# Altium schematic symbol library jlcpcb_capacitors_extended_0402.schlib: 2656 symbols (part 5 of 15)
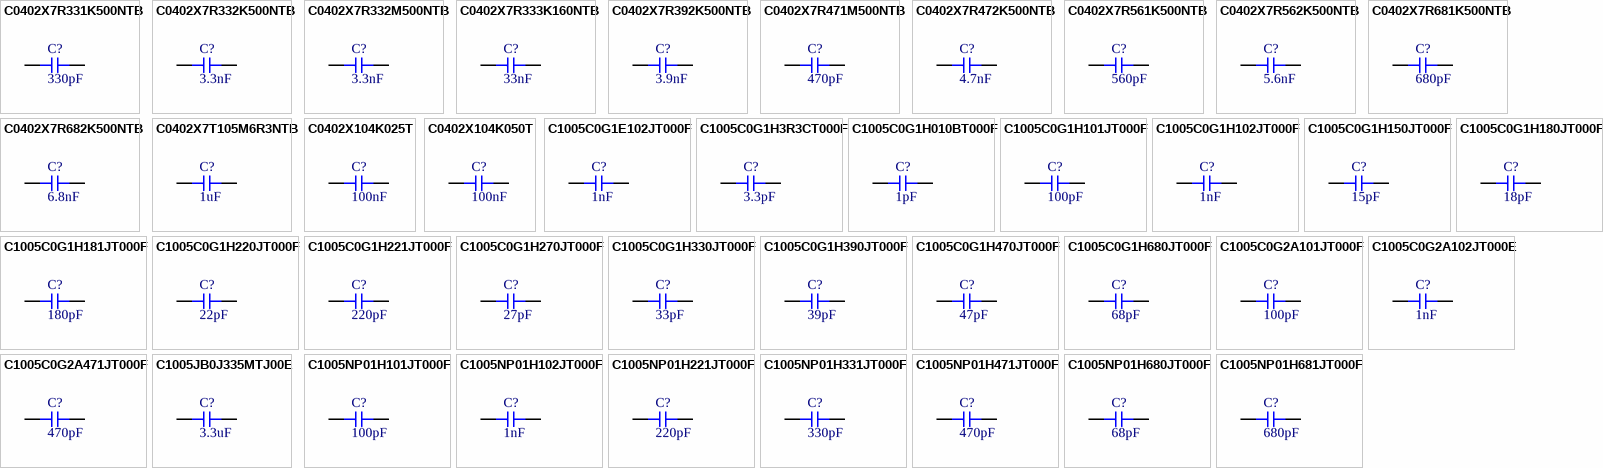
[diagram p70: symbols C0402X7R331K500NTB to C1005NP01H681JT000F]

## C0402X7R331K500NTB
designator C?  Capacitance: 330pF  (hidden comment: *)
Capacitor, Ceramic (MLCC), 330pF, ±10%, 50V, X7R, ±10%, SMD 0402; Manufacturer: EYANG(Shenzhen Eyang Tech Development); Manufacturer Part Number: C0402X7R331K500NTB
footprint CAP-0402 (0402 (1005M) Capacitor)
pins: 1, 2

## C0402X7R332K500NTB
designator C?  Capacitance: 3.3nF  (hidden comment: *)
Capacitor, Ceramic (MLCC), 3.3nF, ±10%, 50V, X7R, ±10%, SMD 0402; Manufacturer: EYANG(Shenzhen Eyang Tech Development); Manufacturer Part Number: C0402X7R332K500NTB
footprint CAP-0402 (0402 (1005M) Capacitor)
pins: 1, 2

## C0402X7R332M500NTB
designator C?  Capacitance: 3.3nF  (hidden comment: *)
Capacitor, Ceramic (MLCC), 3.3nF, ±20%, 50V, X7R, ±20%, SMD 0402; Manufacturer: EYANG(Shenzhen Eyang Tech Development); Manufacturer Part Number: C0402X7R332M500NTB
footprint CAP-0402 (0402 (1005M) Capacitor)
pins: 1, 2

## C0402X7R333K160NTB
designator C?  Capacitance: 33nF  (hidden comment: *)
Capacitor, Ceramic (MLCC), 33nF, ±10%, 16V, X7R, ±10%, SMD 0402; Manufacturer: EYANG(Shenzhen Eyang Tech Development); Manufacturer Part Number: C0402X7R333K160NTB
footprint CAP-0402 (0402 (1005M) Capacitor)
pins: 1, 2

## C0402X7R392K500NTB
designator C?  Capacitance: 3.9nF  (hidden comment: *)
Capacitor, Ceramic (MLCC), 3.9nF, ±10%, 50V, X7R, ±10%, SMD 0402; Manufacturer: EYANG(Shenzhen Eyang Tech Development); Manufacturer Part Number: C0402X7R392K500NTB
footprint CAP-0402 (0402 (1005M) Capacitor)
pins: 1, 2

## C0402X7R471M500NTB
designator C?  Capacitance: 470pF  (hidden comment: *)
Capacitor, Ceramic (MLCC), 470pF, ±20%, 50V, X7R, ±20%, SMD 0402; Manufacturer: EYANG(Shenzhen Eyang Tech Development); Manufacturer Part Number: C0402X7R471M500NTB
footprint CAP-0402 (0402 (1005M) Capacitor)
pins: 1, 2

## C0402X7R472K500NTB
designator C?  Capacitance: 4.7nF  (hidden comment: *)
Capacitor, Ceramic (MLCC), 4.7nF, ±10%, 50V, X7R, ±10%, SMD 0402; Manufacturer: EYANG(Shenzhen Eyang Tech Development); Manufacturer Part Number: C0402X7R472K500NTB
footprint CAP-0402 (0402 (1005M) Capacitor)
pins: 1, 2

## C0402X7R561K500NTB
designator C?  Capacitance: 560pF  (hidden comment: *)
Capacitor, Ceramic (MLCC), 560pF, ±10%, 50V, X7R, ±10%, SMD 0402; Manufacturer: EYANG(Shenzhen Eyang Tech Development); Manufacturer Part Number: C0402X7R561K500NTB
footprint CAP-0402 (0402 (1005M) Capacitor)
pins: 1, 2

## C0402X7R562K500NTB
designator C?  Capacitance: 5.6nF  (hidden comment: *)
Capacitor, Ceramic (MLCC), 5.6nF, ±10%, 50V, X7R, ±10%, SMD 0402; Manufacturer: EYANG(Shenzhen Eyang Tech Development); Manufacturer Part Number: C0402X7R562K500NTB
footprint CAP-0402 (0402 (1005M) Capacitor)
pins: 1, 2

## C0402X7R681K500NTB
designator C?  Capacitance: 680pF  (hidden comment: *)
Capacitor, Ceramic (MLCC), 680pF, ±10%, 50V, X7R, ±10%, SMD 0402; Manufacturer: EYANG(Shenzhen Eyang Tech Development); Manufacturer Part Number: C0402X7R681K500NTB
footprint CAP-0402 (0402 (1005M) Capacitor)
pins: 1, 2

## C0402X7R682K500NTB
designator C?  Capacitance: 6.8nF  (hidden comment: *)
Capacitor, Ceramic (MLCC), 6.8nF, ±10%, 50V, X7R, ±10%, SMD 0402; Manufacturer: EYANG(Shenzhen Eyang Tech Development); Manufacturer Part Number: C0402X7R682K500NTB
footprint CAP-0402 (0402 (1005M) Capacitor)
pins: 1, 2

## C0402X7T105M6R3NTB
designator C?  Capacitance: 1uF  (hidden comment: *)
Capacitor, Ceramic (MLCC), 1uF, ±20%, 6.3V, X7T, ±20%, SMD 0402; Manufacturer: EYANG(Shenzhen Eyang Tech Development); Manufacturer Part Number: C0402X7T105M6R3NTB
footprint CAP-0402 (0402 (1005M) Capacitor)
pins: 1, 2

## C0402X104K025T
designator C?  Capacitance: 100nF  (hidden comment: *)
Capacitor, Ceramic (MLCC), 100nF, ±10%, 25V, X7R, ±10%, SMD 0402; Manufacturer: IHHEC(HOLY STONE ENTERPRISE CO., LTD); Manufacturer Part Number: C0402X104K025T
footprint CAP-0402 (0402 (1005M) Capacitor)
pins: 1, 2

## C0402X104K050T
designator C?  Capacitance: 100nF  (hidden comment: *)
Capacitor, Ceramic (MLCC), 100nF, ±10%, 50V, X7R, ±10%, SMD 0402; Manufacturer: IHHEC(HOLY STONE ENTERPRISE CO., LTD); Manufacturer Part Number: C0402X104K050T
footprint CAP-0402 (0402 (1005M) Capacitor)
pins: 1, 2

## C1005C0G1E102JT000F
designator C?  Capacitance: 1nF  (hidden comment: *)
Capacitor, Ceramic (MLCC), 1nF, ±5%, 25V, C0G, ±5%, SMD 0402; Manufacturer: TDK; Manufacturer Part Number: C1005C0G1E102JT000F
footprint CAP-0402 (0402 (1005M) Capacitor)
pins: 1, 2

## C1005C0G1H3R3CT000F
designator C?  Capacitance: 3.3pF  (hidden comment: *)
Capacitor, Ceramic (MLCC), 3.3pF, ±0.25pF, 50V, C0G, ±0.25pF, SMD 0402; Manufacturer: TDK; Manufacturer Part Number: C1005C0G1H3R3CT000F
footprint CAP-0402 (0402 (1005M) Capacitor)
pins: 1, 2

## C1005C0G1H010BT000F
designator C?  Capacitance: 1pF  (hidden comment: *)
Capacitor, Ceramic (MLCC), 1pF, ±0.1pF, 50V, C0G, ±0.1pF, SMD 0402; Manufacturer: TDK; Manufacturer Part Number: C1005C0G1H010BT000F
footprint CAP-0402 (0402 (1005M) Capacitor)
pins: 1, 2

## C1005C0G1H101JT000F
designator C?  Capacitance: 100pF  (hidden comment: *)
Capacitor, Ceramic (MLCC), 100pF, ±5%, 50V, C0G, ±5%, SMD 0402; Manufacturer: TDK; Manufacturer Part Number: C1005C0G1H101JT000F
footprint CAP-0402 (0402 (1005M) Capacitor)
pins: 1, 2

## C1005C0G1H102JT000F
designator C?  Capacitance: 1nF  (hidden comment: *)
Capacitor, Ceramic (MLCC), 1nF, ±5%, 50V, C0G, ±5%, SMD 0402; Manufacturer: TDK; Manufacturer Part Number: C1005C0G1H102JT000F
footprint CAP-0402 (0402 (1005M) Capacitor)
pins: 1, 2

## C1005C0G1H150JT000F
designator C?  Capacitance: 15pF  (hidden comment: *)
Capacitor, Ceramic (MLCC), 15pF, ±5%, 50V, C0G, ±5%, SMD 0402; Manufacturer: TDK; Manufacturer Part Number: C1005C0G1H150JT000F
footprint CAP-0402 (0402 (1005M) Capacitor)
pins: 1, 2

## C1005C0G1H180JT000F
designator C?  Capacitance: 18pF  (hidden comment: *)
Capacitor, Ceramic (MLCC), 18pF, ±5%, 50V, C0G, ±5%, SMD 0402; Manufacturer: TDK; Manufacturer Part Number: C1005C0G1H180JT000F
footprint CAP-0402 (0402 (1005M) Capacitor)
pins: 1, 2

## C1005C0G1H181JT000F
designator C?  Capacitance: 180pF  (hidden comment: *)
Capacitor, Ceramic (MLCC), 180pF, ±5%, 50V, C0G, ±5%, SMD 0402; Manufacturer: TDK; Manufacturer Part Number: C1005C0G1H181JT000F
footprint CAP-0402 (0402 (1005M) Capacitor)
pins: 1, 2

## C1005C0G1H220JT000F
designator C?  Capacitance: 22pF  (hidden comment: *)
Capacitor, Ceramic (MLCC), 22pF, ±5%, 50V, C0G, ±5%, SMD 0402; Manufacturer: TDK; Manufacturer Part Number: C1005C0G1H220JT000F
footprint CAP-0402 (0402 (1005M) Capacitor)
pins: 1, 2

## C1005C0G1H221JT000F
designator C?  Capacitance: 220pF  (hidden comment: *)
Capacitor, Ceramic (MLCC), 220pF, ±5%, 50V, C0G, ±5%, SMD 0402; Manufacturer: TDK; Manufacturer Part Number: C1005C0G1H221JT000F
footprint CAP-0402 (0402 (1005M) Capacitor)
pins: 1, 2

## C1005C0G1H270JT000F
designator C?  Capacitance: 27pF  (hidden comment: *)
Capacitor, Ceramic (MLCC), 27pF, ±5%, 50V, C0G, ±5%, SMD 0402; Manufacturer: TDK; Manufacturer Part Number: C1005C0G1H270JT000F
footprint CAP-0402 (0402 (1005M) Capacitor)
pins: 1, 2

## C1005C0G1H330JT000F
designator C?  Capacitance: 33pF  (hidden comment: *)
Capacitor, Ceramic (MLCC), 33pF, ±5%, 50V, C0G, ±5%, SMD 0402; Manufacturer: TDK; Manufacturer Part Number: C1005C0G1H330JT000F
footprint CAP-0402 (0402 (1005M) Capacitor)
pins: 1, 2

## C1005C0G1H390JT000F
designator C?  Capacitance: 39pF  (hidden comment: *)
Capacitor, Ceramic (MLCC), 39pF, ±5%, 50V, C0G, ±5%, SMD 0402; Manufacturer: TDK; Manufacturer Part Number: C1005C0G1H390JT000F
footprint CAP-0402 (0402 (1005M) Capacitor)
pins: 1, 2

## C1005C0G1H470JT000F
designator C?  Capacitance: 47pF  (hidden comment: *)
Capacitor, Ceramic (MLCC), 47pF, ±5%, 50V, C0G, ±5%, SMD 0402; Manufacturer: TDK; Manufacturer Part Number: C1005C0G1H470JT000F
footprint CAP-0402 (0402 (1005M) Capacitor)
pins: 1, 2

## C1005C0G1H680JT000F
designator C?  Capacitance: 68pF  (hidden comment: *)
Capacitor, Ceramic (MLCC), 68pF, ±5%, 50V, C0G, ±5%, SMD 0402; Manufacturer: TDK; Manufacturer Part Number: C1005C0G1H680JT000F
footprint CAP-0402 (0402 (1005M) Capacitor)
pins: 1, 2

## C1005C0G2A101JT000F
designator C?  Capacitance: 100pF  (hidden comment: *)
Capacitor, Ceramic (MLCC), 100pF, ±5%, 100V, C0G, ±5%, SMD 0402; Manufacturer: TDK; Manufacturer Part Number: C1005C0G2A101JT000F
footprint CAP-0402 (0402 (1005M) Capacitor)
pins: 1, 2

## C1005C0G2A102JT000E
designator C?  Capacitance: 1nF  (hidden comment: *)
Capacitor, Ceramic (MLCC), 1nF, ±5%, 100V, C0G, ±5%, SMD 0402; Manufacturer: TDK; Manufacturer Part Number: C1005C0G2A102JT000E
footprint CAP-0402 (0402 (1005M) Capacitor)
pins: 1, 2

## C1005C0G2A471JT000F
designator C?  Capacitance: 470pF  (hidden comment: *)
Capacitor, Ceramic (MLCC), 470pF, ±5%, 100V, C0G, ±5%, SMD 0402; Manufacturer: TDK; Manufacturer Part Number: C1005C0G2A471JT000F
footprint CAP-0402 (0402 (1005M) Capacitor)
pins: 1, 2

## C1005JB0J335MTJ00E
designator C?  Capacitance: 3.3uF  (hidden comment: *)
Capacitor, Ceramic (MLCC), 3.3uF, ±20%, 6.3V, ±20%, SMD 0402; Manufacturer: TDK; Manufacturer Part Number: C1005JB0J335MTJ00E
footprint CAP-0402 (0402 (1005M) Capacitor)
pins: 1, 2

## C1005NP01H101JT000F
designator C?  Capacitance: 100pF  (hidden comment: *)
Capacitor, Ceramic (MLCC), 100pF, ±5%, 50V, NP0, ±5%, SMD 0402; Manufacturer: TDK; Manufacturer Part Number: C1005NP01H101JT000F
footprint CAP-0402 (0402 (1005M) Capacitor)
pins: 1, 2

## C1005NP01H102JT000F
designator C?  Capacitance: 1nF  (hidden comment: *)
Capacitor, Ceramic (MLCC), 1nF, ±5%, 50V, NP0, ±5%, SMD 0402; Manufacturer: TDK; Manufacturer Part Number: C1005NP01H102JT000F
footprint CAP-0402 (0402 (1005M) Capacitor)
pins: 1, 2

## C1005NP01H221JT000F
designator C?  Capacitance: 220pF  (hidden comment: *)
Capacitor, Ceramic (MLCC), 220pF, ±5%, 50V, NP0, ±5%, SMD 0402; Manufacturer: TDK; Manufacturer Part Number: C1005NP01H221JT000F
footprint CAP-0402 (0402 (1005M) Capacitor)
pins: 1, 2

## C1005NP01H331JT000F
designator C?  Capacitance: 330pF  (hidden comment: *)
Capacitor, Ceramic (MLCC), 330pF, ±5%, 50V, NP0, ±5%, SMD 0402; Manufacturer: TDK; Manufacturer Part Number: C1005NP01H331JT000F
footprint CAP-0402 (0402 (1005M) Capacitor)
pins: 1, 2

## C1005NP01H471JT000F
designator C?  Capacitance: 470pF  (hidden comment: *)
Capacitor, Ceramic (MLCC), 470pF, ±5%, 50V, NP0, ±5%, SMD 0402; Manufacturer: TDK; Manufacturer Part Number: C1005NP01H471JT000F
footprint CAP-0402 (0402 (1005M) Capacitor)
pins: 1, 2

## C1005NP01H680JT000F
designator C?  Capacitance: 68pF  (hidden comment: *)
Capacitor, Ceramic (MLCC), 68pF, ±5%, 50V, NP0, ±5%, SMD 0402; Manufacturer: TDK; Manufacturer Part Number: C1005NP01H680JT000F
footprint CAP-0402 (0402 (1005M) Capacitor)
pins: 1, 2

## C1005NP01H681JT000F
designator C?  Capacitance: 680pF  (hidden comment: *)
Capacitor, Ceramic (MLCC), 680pF, ±5%, 50V, NP0, ±5%, SMD 0402; Manufacturer: TDK; Manufacturer Part Number: C1005NP01H681JT000F
footprint CAP-0402 (0402 (1005M) Capacitor)
pins: 1, 2

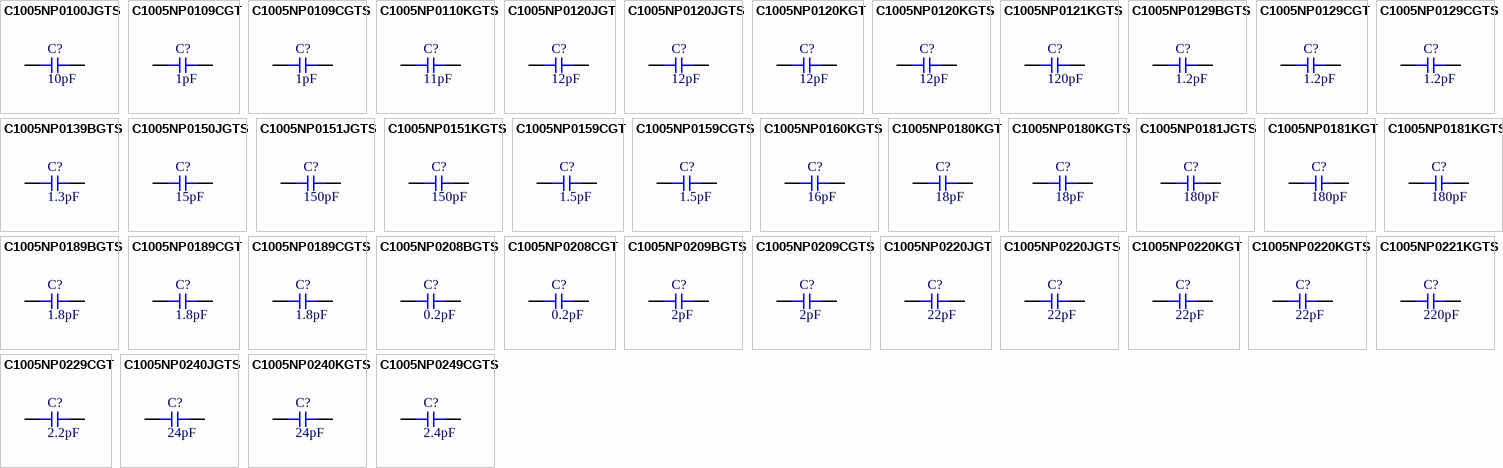
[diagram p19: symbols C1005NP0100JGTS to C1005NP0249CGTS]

## C1005NP0100JGTS
designator C?  Capacitance: 10pF  (hidden comment: *)
Capacitor, Ceramic (MLCC), 10pF, ±5%, 50V, NP0, ±5%, SMD 0402; Manufacturer: Darfon Elec; Manufacturer Part Number: C1005NP0100JGTS
footprint CAP-0402 (0402 (1005M) Capacitor)
pins: 1, 2

## C1005NP0109CGT
designator C?  Capacitance: 1pF  (hidden comment: *)
Capacitor, Ceramic (MLCC), 1pF, ±0.25pF, 50V, NP0, ±0.25pF, SMD 0402; Manufacturer: Darfon Elec; Manufacturer Part Number: C1005NP0109CGT
footprint CAP-0402 (0402 (1005M) Capacitor)
pins: 1, 2

## C1005NP0109CGTS
designator C?  Capacitance: 1pF  (hidden comment: *)
Capacitor, Ceramic (MLCC), 1pF, ±0.25pF, 50V, NP0, ±0.25pF, SMD 0402; Manufacturer: Darfon Elec; Manufacturer Part Number: C1005NP0109CGTS
footprint CAP-0402 (0402 (1005M) Capacitor)
pins: 1, 2

## C1005NP0110KGTS
designator C?  Capacitance: 11pF  (hidden comment: *)
Capacitor, Ceramic (MLCC), 11pF, ±10%, 50V, NP0, ±10%, SMD 0402; Manufacturer: Darfon Elec; Manufacturer Part Number: C1005NP0110KGTS
footprint CAP-0402 (0402 (1005M) Capacitor)
pins: 1, 2

## C1005NP0120JGT
designator C?  Capacitance: 12pF  (hidden comment: *)
Capacitor, Ceramic (MLCC), 12pF, ±5%, 50V, NP0, ±5%, SMD 0402; Manufacturer: Darfon Elec; Manufacturer Part Number: C1005NP0120JGT
footprint CAP-0402 (0402 (1005M) Capacitor)
pins: 1, 2

## C1005NP0120JGTS
designator C?  Capacitance: 12pF  (hidden comment: *)
Capacitor, Ceramic (MLCC), 12pF, ±5%, 50V, NP0, ±5%, SMD 0402; Manufacturer: Darfon Elec; Manufacturer Part Number: C1005NP0120JGTS
footprint CAP-0402 (0402 (1005M) Capacitor)
pins: 1, 2

## C1005NP0120KGT
designator C?  Capacitance: 12pF  (hidden comment: *)
Capacitor, Ceramic (MLCC), 12pF, ±10%, 50V, NP0, ±10%, SMD 0402; Manufacturer: Darfon Elec; Manufacturer Part Number: C1005NP0120KGT
footprint CAP-0402 (0402 (1005M) Capacitor)
pins: 1, 2

## C1005NP0120KGTS
designator C?  Capacitance: 12pF  (hidden comment: *)
Capacitor, Ceramic (MLCC), 12pF, ±10%, 50V, NP0, ±10%, SMD 0402; Manufacturer: Darfon Elec; Manufacturer Part Number: C1005NP0120KGTS
footprint CAP-0402 (0402 (1005M) Capacitor)
pins: 1, 2

## C1005NP0121KGTS
designator C?  Capacitance: 120pF  (hidden comment: *)
Capacitor, Ceramic (MLCC), 120pF, ±10%, 50V, NP0, ±10%, SMD 0402; Manufacturer: Darfon Elec; Manufacturer Part Number: C1005NP0121KGTS
footprint CAP-0402 (0402 (1005M) Capacitor)
pins: 1, 2

## C1005NP0129BGTS
designator C?  Capacitance: 1.2pF  (hidden comment: *)
Capacitor, Ceramic (MLCC), 1.2pF, ±0.1pF, 50V, NP0, ±0.1pF, SMD 0402; Manufacturer: Darfon Elec; Manufacturer Part Number: C1005NP0129BGTS
footprint CAP-0402 (0402 (1005M) Capacitor)
pins: 1, 2

## C1005NP0129CGT
designator C?  Capacitance: 1.2pF  (hidden comment: *)
Capacitor, Ceramic (MLCC), 1.2pF, ±0.25pF, 50V, NP0, ±0.25pF, SMD 0402; Manufacturer: Darfon Elec; Manufacturer Part Number: C1005NP0129CGT
footprint CAP-0402 (0402 (1005M) Capacitor)
pins: 1, 2

## C1005NP0129CGTS
designator C?  Capacitance: 1.2pF  (hidden comment: *)
Capacitor, Ceramic (MLCC), 1.2pF, ±0.25pF, 50V, NP0, ±0.25pF, SMD 0402; Manufacturer: Darfon Elec; Manufacturer Part Number: C1005NP0129CGTS
footprint CAP-0402 (0402 (1005M) Capacitor)
pins: 1, 2

## C1005NP0139BGTS
designator C?  Capacitance: 1.3pF  (hidden comment: *)
Capacitor, Ceramic (MLCC), 1.3pF, ±0.1pF, 50V, NP0, ±0.1pF, SMD 0402; Manufacturer: Darfon Elec; Manufacturer Part Number: C1005NP0139BGTS
footprint CAP-0402 (0402 (1005M) Capacitor)
pins: 1, 2

## C1005NP0150JGTS
designator C?  Capacitance: 15pF  (hidden comment: *)
Capacitor, Ceramic (MLCC), 15pF, ±5%, 50V, NP0, ±5%, SMD 0402; Manufacturer: Darfon Elec; Manufacturer Part Number: C1005NP0150JGTS
footprint CAP-0402 (0402 (1005M) Capacitor)
pins: 1, 2

## C1005NP0151JGTS
designator C?  Capacitance: 150pF  (hidden comment: *)
Capacitor, Ceramic (MLCC), 150pF, ±5%, 50V, NP0, ±5%, SMD 0402; Manufacturer: Darfon Elec; Manufacturer Part Number: C1005NP0151JGTS
footprint CAP-0402 (0402 (1005M) Capacitor)
pins: 1, 2

## C1005NP0151KGTS
designator C?  Capacitance: 150pF  (hidden comment: *)
Capacitor, Ceramic (MLCC), 150pF, ±10%, 50V, NP0, ±10%, SMD 0402; Manufacturer: Darfon Elec; Manufacturer Part Number: C1005NP0151KGTS
footprint CAP-0402 (0402 (1005M) Capacitor)
pins: 1, 2

## C1005NP0159CGT
designator C?  Capacitance: 1.5pF  (hidden comment: *)
Capacitor, Ceramic (MLCC), 1.5pF, ±0.25pF, 50V, NP0, ±0.25pF, SMD 0402; Manufacturer: Darfon Elec; Manufacturer Part Number: C1005NP0159CGT
footprint CAP-0402 (0402 (1005M) Capacitor)
pins: 1, 2

## C1005NP0159CGTS
designator C?  Capacitance: 1.5pF  (hidden comment: *)
Capacitor, Ceramic (MLCC), 1.5pF, ±0.25pF, 50V, NP0, ±0.25pF, SMD 0402; Manufacturer: Darfon Elec; Manufacturer Part Number: C1005NP0159CGTS
footprint CAP-0402 (0402 (1005M) Capacitor)
pins: 1, 2

## C1005NP0160KGTS
designator C?  Capacitance: 16pF  (hidden comment: *)
Capacitor, Ceramic (MLCC), 16pF, ±10%, 50V, NP0, ±10%, SMD 0402; Manufacturer: Darfon Elec; Manufacturer Part Number: C1005NP0160KGTS
footprint CAP-0402 (0402 (1005M) Capacitor)
pins: 1, 2

## C1005NP0180KGT
designator C?  Capacitance: 18pF  (hidden comment: *)
Capacitor, Ceramic (MLCC), 18pF, ±10%, 50V, NP0, ±10%, SMD 0402; Manufacturer: Darfon Elec; Manufacturer Part Number: C1005NP0180KGT
footprint CAP-0402 (0402 (1005M) Capacitor)
pins: 1, 2

## C1005NP0180KGTS
designator C?  Capacitance: 18pF  (hidden comment: *)
Capacitor, Ceramic (MLCC), 18pF, ±10%, 50V, NP0, ±10%, SMD 0402; Manufacturer: Darfon Elec; Manufacturer Part Number: C1005NP0180KGTS
footprint CAP-0402 (0402 (1005M) Capacitor)
pins: 1, 2

## C1005NP0181JGTS
designator C?  Capacitance: 180pF  (hidden comment: *)
Capacitor, Ceramic (MLCC), 180pF, ±5%, 50V, NP0, ±5%, SMD 0402; Manufacturer: Darfon Elec; Manufacturer Part Number: C1005NP0181JGTS
footprint CAP-0402 (0402 (1005M) Capacitor)
pins: 1, 2

## C1005NP0181KGT
designator C?  Capacitance: 180pF  (hidden comment: *)
Capacitor, Ceramic (MLCC), 180pF, ±10%, 50V, NP0, ±10%, SMD 0402; Manufacturer: Darfon Elec; Manufacturer Part Number: C1005NP0181KGT
footprint CAP-0402 (0402 (1005M) Capacitor)
pins: 1, 2

## C1005NP0181KGTS
designator C?  Capacitance: 180pF  (hidden comment: *)
Capacitor, Ceramic (MLCC), 180pF, ±10%, 50V, NP0, ±10%, SMD 0402; Manufacturer: Darfon Elec; Manufacturer Part Number: C1005NP0181KGTS
footprint CAP-0402 (0402 (1005M) Capacitor)
pins: 1, 2

## C1005NP0189BGTS
designator C?  Capacitance: 1.8pF  (hidden comment: *)
Capacitor, Ceramic (MLCC), 1.8pF, ±0.1pF, 50V, NP0, ±0.1pF, SMD 0402; Manufacturer: Darfon Elec; Manufacturer Part Number: C1005NP0189BGTS
footprint CAP-0402 (0402 (1005M) Capacitor)
pins: 1, 2

## C1005NP0189CGT
designator C?  Capacitance: 1.8pF  (hidden comment: *)
Capacitor, Ceramic (MLCC), 1.8pF, ±0.25pF, 50V, NP0, ±0.25pF, SMD 0402; Manufacturer: Darfon Elec; Manufacturer Part Number: C1005NP0189CGT
footprint CAP-0402 (0402 (1005M) Capacitor)
pins: 1, 2

## C1005NP0189CGTS
designator C?  Capacitance: 1.8pF  (hidden comment: *)
Capacitor, Ceramic (MLCC), 1.8pF, ±0.25pF, 50V, NP0, ±0.25pF, SMD 0402; Manufacturer: Darfon Elec; Manufacturer Part Number: C1005NP0189CGTS
footprint CAP-0402 (0402 (1005M) Capacitor)
pins: 1, 2

## C1005NP0208BGTS
designator C?  Capacitance: 0.2pF  (hidden comment: *)
Capacitor, Ceramic (MLCC), 0.2pF, ±0.1pF, 50V, NP0, ±0.1pF, SMD 0402; Manufacturer: Darfon Elec; Manufacturer Part Number: C1005NP0208BGTS
footprint CAP-0402 (0402 (1005M) Capacitor)
pins: 1, 2

## C1005NP0208CGT
designator C?  Capacitance: 0.2pF  (hidden comment: *)
Capacitor, Ceramic (MLCC), 0.2pF, ±0.25pF, 50V, NP0, ±0.25pF, SMD 0402; Manufacturer: Darfon Elec; Manufacturer Part Number: C1005NP0208CGT
footprint CAP-0402 (0402 (1005M) Capacitor)
pins: 1, 2

## C1005NP0209BGTS
designator C?  Capacitance: 2pF  (hidden comment: *)
Capacitor, Ceramic (MLCC), 2pF, ±0.1pF, 50V, NP0, ±0.1pF, SMD 0402; Manufacturer: Darfon Elec; Manufacturer Part Number: C1005NP0209BGTS
footprint CAP-0402 (0402 (1005M) Capacitor)
pins: 1, 2

## C1005NP0209CGTS
designator C?  Capacitance: 2pF  (hidden comment: *)
Capacitor, Ceramic (MLCC), 2pF, ±0.25pF, 50V, NP0, ±0.25pF, SMD 0402; Manufacturer: Darfon Elec; Manufacturer Part Number: C1005NP0209CGTS
footprint CAP-0402 (0402 (1005M) Capacitor)
pins: 1, 2

## C1005NP0220JGT
designator C?  Capacitance: 22pF  (hidden comment: *)
Capacitor, Ceramic (MLCC), 22pF, ±5%, 50V, NP0, ±5%, SMD 0402; Manufacturer: Darfon Elec; Manufacturer Part Number: C1005NP0220JGT
footprint CAP-0402 (0402 (1005M) Capacitor)
pins: 1, 2

## C1005NP0220JGTS
designator C?  Capacitance: 22pF  (hidden comment: *)
Capacitor, Ceramic (MLCC), 22pF, ±5%, 50V, NP0, ±5%, SMD 0402; Manufacturer: Darfon Elec; Manufacturer Part Number: C1005NP0220JGTS
footprint CAP-0402 (0402 (1005M) Capacitor)
pins: 1, 2

## C1005NP0220KGT
designator C?  Capacitance: 22pF  (hidden comment: *)
Capacitor, Ceramic (MLCC), 22pF, ±10%, 50V, NP0, ±10%, SMD 0402; Manufacturer: Darfon Elec; Manufacturer Part Number: C1005NP0220KGT
footprint CAP-0402 (0402 (1005M) Capacitor)
pins: 1, 2

## C1005NP0220KGTS
designator C?  Capacitance: 22pF  (hidden comment: *)
Capacitor, Ceramic (MLCC), 22pF, ±10%, 50V, NP0, ±10%, SMD 0402; Manufacturer: Darfon Elec; Manufacturer Part Number: C1005NP0220KGTS
footprint CAP-0402 (0402 (1005M) Capacitor)
pins: 1, 2

## C1005NP0221KGTS
designator C?  Capacitance: 220pF  (hidden comment: *)
Capacitor, Ceramic (MLCC), 220pF, ±10%, 50V, NP0, ±10%, SMD 0402; Manufacturer: Darfon Elec; Manufacturer Part Number: C1005NP0221KGTS
footprint CAP-0402 (0402 (1005M) Capacitor)
pins: 1, 2

## C1005NP0229CGT
designator C?  Capacitance: 2.2pF  (hidden comment: *)
Capacitor, Ceramic (MLCC), 2.2pF, ±0.25pF, 50V, NP0, ±0.25pF, SMD 0402; Manufacturer: Darfon Elec; Manufacturer Part Number: C1005NP0229CGT
footprint CAP-0402 (0402 (1005M) Capacitor)
pins: 1, 2

## C1005NP0240JGTS
designator C?  Capacitance: 24pF  (hidden comment: *)
Capacitor, Ceramic (MLCC), 24pF, ±5%, 50V, NP0, ±5%, SMD 0402; Manufacturer: Darfon Elec; Manufacturer Part Number: C1005NP0240JGTS
footprint CAP-0402 (0402 (1005M) Capacitor)
pins: 1, 2

## C1005NP0240KGTS
designator C?  Capacitance: 24pF  (hidden comment: *)
Capacitor, Ceramic (MLCC), 24pF, ±10%, 50V, NP0, ±10%, SMD 0402; Manufacturer: Darfon Elec; Manufacturer Part Number: C1005NP0240KGTS
footprint CAP-0402 (0402 (1005M) Capacitor)
pins: 1, 2

## C1005NP0249CGTS
designator C?  Capacitance: 2.4pF  (hidden comment: *)
Capacitor, Ceramic (MLCC), 2.4pF, ±0.25pF, 50V, NP0, ±0.25pF, SMD 0402; Manufacturer: Darfon Elec; Manufacturer Part Number: C1005NP0249CGTS
footprint CAP-0402 (0402 (1005M) Capacitor)
pins: 1, 2

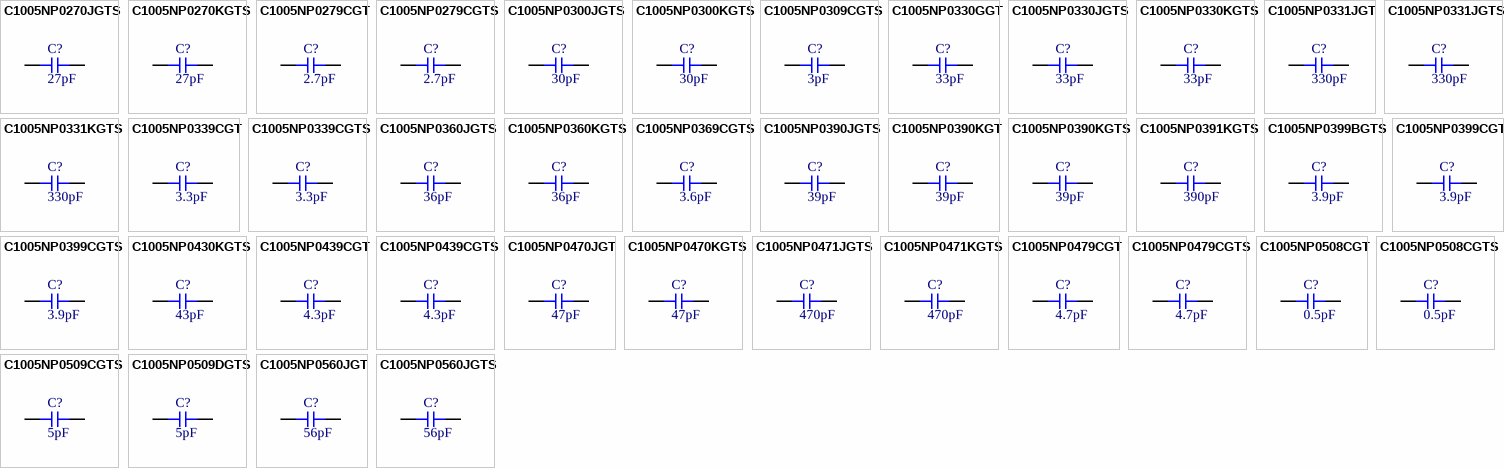
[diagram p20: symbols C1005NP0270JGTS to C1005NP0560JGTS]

## C1005NP0270JGTS
designator C?  Capacitance: 27pF  (hidden comment: *)
Capacitor, Ceramic (MLCC), 27pF, ±5%, 50V, NP0, ±5%, SMD 0402; Manufacturer: Darfon Elec; Manufacturer Part Number: C1005NP0270JGTS
footprint CAP-0402 (0402 (1005M) Capacitor)
pins: 1, 2

## C1005NP0270KGTS
designator C?  Capacitance: 27pF  (hidden comment: *)
Capacitor, Ceramic (MLCC), 27pF, ±10%, 50V, NP0, ±10%, SMD 0402; Manufacturer: Darfon Elec; Manufacturer Part Number: C1005NP0270KGTS
footprint CAP-0402 (0402 (1005M) Capacitor)
pins: 1, 2

## C1005NP0279CGT
designator C?  Capacitance: 2.7pF  (hidden comment: *)
Capacitor, Ceramic (MLCC), 2.7pF, ±0.25pF, 50V, NP0, ±0.25pF, SMD 0402; Manufacturer: Darfon Elec; Manufacturer Part Number: C1005NP0279CGT
footprint CAP-0402 (0402 (1005M) Capacitor)
pins: 1, 2

## C1005NP0279CGTS
designator C?  Capacitance: 2.7pF  (hidden comment: *)
Capacitor, Ceramic (MLCC), 2.7pF, ±0.25pF, 50V, NP0, ±0.25pF, SMD 0402; Manufacturer: Darfon Elec; Manufacturer Part Number: C1005NP0279CGTS
footprint CAP-0402 (0402 (1005M) Capacitor)
pins: 1, 2

## C1005NP0300JGTS
designator C?  Capacitance: 30pF  (hidden comment: *)
Capacitor, Ceramic (MLCC), 30pF, ±5%, 50V, NP0, ±5%, SMD 0402; Manufacturer: Darfon Elec; Manufacturer Part Number: C1005NP0300JGTS
footprint CAP-0402 (0402 (1005M) Capacitor)
pins: 1, 2

## C1005NP0300KGTS
designator C?  Capacitance: 30pF  (hidden comment: *)
Capacitor, Ceramic (MLCC), 30pF, ±10%, 50V, NP0, ±10%, SMD 0402; Manufacturer: Darfon Elec; Manufacturer Part Number: C1005NP0300KGTS
footprint CAP-0402 (0402 (1005M) Capacitor)
pins: 1, 2

## C1005NP0309CGTS
designator C?  Capacitance: 3pF  (hidden comment: *)
Capacitor, Ceramic (MLCC), 3pF, ±0.25pF, 50V, NP0, ±0.25pF, SMD 0402; Manufacturer: Darfon Elec; Manufacturer Part Number: C1005NP0309CGTS
footprint CAP-0402 (0402 (1005M) Capacitor)
pins: 1, 2

## C1005NP0330GGT
designator C?  Capacitance: 33pF  (hidden comment: *)
Capacitor, Ceramic (MLCC), 33pF, ±2%, 50V, NP0, ±2%, SMD 0402; Manufacturer: Darfon Elec; Manufacturer Part Number: C1005NP0330GGT
footprint CAP-0402 (0402 (1005M) Capacitor)
pins: 1, 2

## C1005NP0330JGTS
designator C?  Capacitance: 33pF  (hidden comment: *)
Capacitor, Ceramic (MLCC), 33pF, ±5%, 50V, NP0, ±5%, SMD 0402; Manufacturer: Darfon Elec; Manufacturer Part Number: C1005NP0330JGTS
footprint CAP-0402 (0402 (1005M) Capacitor)
pins: 1, 2

## C1005NP0330KGTS
designator C?  Capacitance: 33pF  (hidden comment: *)
Capacitor, Ceramic (MLCC), 33pF, ±10%, 50V, NP0, ±10%, SMD 0402; Manufacturer: Darfon Elec; Manufacturer Part Number: C1005NP0330KGTS
footprint CAP-0402 (0402 (1005M) Capacitor)
pins: 1, 2

## C1005NP0331JGT
designator C?  Capacitance: 330pF  (hidden comment: *)
Capacitor, Ceramic (MLCC), 330pF, ±5%, 50V, NP0, ±5%, SMD 0402; Manufacturer: Darfon Elec; Manufacturer Part Number: C1005NP0331JGT
footprint CAP-0402 (0402 (1005M) Capacitor)
pins: 1, 2

## C1005NP0331JGTS
designator C?  Capacitance: 330pF  (hidden comment: *)
Capacitor, Ceramic (MLCC), 330pF, ±5%, 50V, NP0, ±5%, SMD 0402; Manufacturer: Darfon Elec; Manufacturer Part Number: C1005NP0331JGTS
footprint CAP-0402 (0402 (1005M) Capacitor)
pins: 1, 2

## C1005NP0331KGTS
designator C?  Capacitance: 330pF  (hidden comment: *)
Capacitor, Ceramic (MLCC), 330pF, ±10%, 50V, NP0, ±10%, SMD 0402; Manufacturer: Darfon Elec; Manufacturer Part Number: C1005NP0331KGTS
footprint CAP-0402 (0402 (1005M) Capacitor)
pins: 1, 2

## C1005NP0339CGT
designator C?  Capacitance: 3.3pF  (hidden comment: *)
Capacitor, Ceramic (MLCC), 3.3pF, ±0.25pF, 50V, NP0, ±0.25pF, SMD 0402; Manufacturer: Darfon Elec; Manufacturer Part Number: C1005NP0339CGT
footprint CAP-0402 (0402 (1005M) Capacitor)
pins: 1, 2

## C1005NP0339CGTS
designator C?  Capacitance: 3.3pF  (hidden comment: *)
Capacitor, Ceramic (MLCC), 3.3pF, ±0.25pF, 50V, NP0, ±0.25pF, SMD 0402; Manufacturer: Darfon Elec; Manufacturer Part Number: C1005NP0339CGTS
footprint CAP-0402 (0402 (1005M) Capacitor)
pins: 1, 2

## C1005NP0360JGTS
designator C?  Capacitance: 36pF  (hidden comment: *)
Capacitor, Ceramic (MLCC), 36pF, ±5%, 50V, NP0, ±5%, SMD 0402; Manufacturer: Darfon Elec; Manufacturer Part Number: C1005NP0360JGTS
footprint CAP-0402 (0402 (1005M) Capacitor)
pins: 1, 2

## C1005NP0360KGTS
designator C?  Capacitance: 36pF  (hidden comment: *)
Capacitor, Ceramic (MLCC), 36pF, ±10%, 50V, NP0, ±10%, SMD 0402; Manufacturer: Darfon Elec; Manufacturer Part Number: C1005NP0360KGTS
footprint CAP-0402 (0402 (1005M) Capacitor)
pins: 1, 2

## C1005NP0369CGTS
designator C?  Capacitance: 3.6pF  (hidden comment: *)
Capacitor, Ceramic (MLCC), 3.6pF, ±0.25pF, 50V, NP0, ±0.25pF, SMD 0402; Manufacturer: Darfon Elec; Manufacturer Part Number: C1005NP0369CGTS
footprint CAP-0402 (0402 (1005M) Capacitor)
pins: 1, 2

## C1005NP0390JGTS
designator C?  Capacitance: 39pF  (hidden comment: *)
Capacitor, Ceramic (MLCC), 39pF, ±5%, 50V, NP0, ±5%, SMD 0402; Manufacturer: Darfon Elec; Manufacturer Part Number: C1005NP0390JGTS
footprint CAP-0402 (0402 (1005M) Capacitor)
pins: 1, 2

## C1005NP0390KGT
designator C?  Capacitance: 39pF  (hidden comment: *)
Capacitor, Ceramic (MLCC), 39pF, ±10%, 50V, NP0, ±10%, SMD 0402; Manufacturer: Darfon Elec; Manufacturer Part Number: C1005NP0390KGT
footprint CAP-0402 (0402 (1005M) Capacitor)
pins: 1, 2

## C1005NP0390KGTS
designator C?  Capacitance: 39pF  (hidden comment: *)
Capacitor, Ceramic (MLCC), 39pF, ±10%, 50V, NP0, ±10%, SMD 0402; Manufacturer: Darfon Elec; Manufacturer Part Number: C1005NP0390KGTS
footprint CAP-0402 (0402 (1005M) Capacitor)
pins: 1, 2

## C1005NP0391KGTS
designator C?  Capacitance: 390pF  (hidden comment: *)
Capacitor, Ceramic (MLCC), 390pF, ±10%, 50V, NP0, ±10%, SMD 0402; Manufacturer: Darfon Elec; Manufacturer Part Number: C1005NP0391KGTS
footprint CAP-0402 (0402 (1005M) Capacitor)
pins: 1, 2

## C1005NP0399BGTS
designator C?  Capacitance: 3.9pF  (hidden comment: *)
Capacitor, Ceramic (MLCC), 3.9pF, ±0.1pF, 50V, NP0, ±0.1pF, SMD 0402; Manufacturer: Darfon Elec; Manufacturer Part Number: C1005NP0399BGTS
footprint CAP-0402 (0402 (1005M) Capacitor)
pins: 1, 2

## C1005NP0399CGT
designator C?  Capacitance: 3.9pF  (hidden comment: *)
Capacitor, Ceramic (MLCC), 3.9pF, ±0.25pF, 50V, NP0, ±0.25pF, SMD 0402; Manufacturer: Darfon Elec; Manufacturer Part Number: C1005NP0399CGT
footprint CAP-0402 (0402 (1005M) Capacitor)
pins: 1, 2

## C1005NP0399CGTS
designator C?  Capacitance: 3.9pF  (hidden comment: *)
Capacitor, Ceramic (MLCC), 3.9pF, ±0.25pF, 50V, NP0, ±0.25pF, SMD 0402; Manufacturer: Darfon Elec; Manufacturer Part Number: C1005NP0399CGTS
footprint CAP-0402 (0402 (1005M) Capacitor)
pins: 1, 2

## C1005NP0430KGTS
designator C?  Capacitance: 43pF  (hidden comment: *)
Capacitor, Ceramic (MLCC), 43pF, ±10%, 50V, NP0, ±10%, SMD 0402; Manufacturer: Darfon Elec; Manufacturer Part Number: C1005NP0430KGTS
footprint CAP-0402 (0402 (1005M) Capacitor)
pins: 1, 2

## C1005NP0439CGT
designator C?  Capacitance: 4.3pF  (hidden comment: *)
Capacitor, Ceramic (MLCC), 4.3pF, ±0.25pF, 50V, NP0, ±0.25pF, SMD 0402; Manufacturer: Darfon Elec; Manufacturer Part Number: C1005NP0439CGT
footprint CAP-0402 (0402 (1005M) Capacitor)
pins: 1, 2

## C1005NP0439CGTS
designator C?  Capacitance: 4.3pF  (hidden comment: *)
Capacitor, Ceramic (MLCC), 4.3pF, ±0.25pF, 50V, NP0, ±0.25pF, SMD 0402; Manufacturer: Darfon Elec; Manufacturer Part Number: C1005NP0439CGTS
footprint CAP-0402 (0402 (1005M) Capacitor)
pins: 1, 2

## C1005NP0470JGT
designator C?  Capacitance: 47pF  (hidden comment: *)
Capacitor, Ceramic (MLCC), 47pF, ±5%, 50V, NP0, ±5%, SMD 0402; Manufacturer: Darfon Elec; Manufacturer Part Number: C1005NP0470JGT
footprint CAP-0402 (0402 (1005M) Capacitor)
pins: 1, 2

## C1005NP0470KGTS
designator C?  Capacitance: 47pF  (hidden comment: *)
Capacitor, Ceramic (MLCC), 47pF, ±10%, 50V, NP0, ±10%, SMD 0402; Manufacturer: Darfon Elec; Manufacturer Part Number: C1005NP0470KGTS
footprint CAP-0402 (0402 (1005M) Capacitor)
pins: 1, 2

## C1005NP0471JGTS
designator C?  Capacitance: 470pF  (hidden comment: *)
Capacitor, Ceramic (MLCC), 470pF, ±5%, 50V, NP0, ±5%, SMD 0402; Manufacturer: Darfon Elec; Manufacturer Part Number: C1005NP0471JGTS
footprint CAP-0402 (0402 (1005M) Capacitor)
pins: 1, 2

## C1005NP0471KGTS
designator C?  Capacitance: 470pF  (hidden comment: *)
Capacitor, Ceramic (MLCC), 470pF, ±10%, 50V, NP0, ±10%, SMD 0402; Manufacturer: Darfon Elec; Manufacturer Part Number: C1005NP0471KGTS
footprint CAP-0402 (0402 (1005M) Capacitor)
pins: 1, 2

## C1005NP0479CGT
designator C?  Capacitance: 4.7pF  (hidden comment: *)
Capacitor, Ceramic (MLCC), 4.7pF, ±0.25pF, 50V, NP0, ±0.25pF, SMD 0402; Manufacturer: Darfon Elec; Manufacturer Part Number: C1005NP0479CGT
footprint CAP-0402 (0402 (1005M) Capacitor)
pins: 1, 2

## C1005NP0479CGTS
designator C?  Capacitance: 4.7pF  (hidden comment: *)
Capacitor, Ceramic (MLCC), 4.7pF, ±0.25pF, 50V, NP0, ±0.25pF, SMD 0402; Manufacturer: Darfon Elec; Manufacturer Part Number: C1005NP0479CGTS
footprint CAP-0402 (0402 (1005M) Capacitor)
pins: 1, 2

## C1005NP0508CGT
designator C?  Capacitance: 0.5pF  (hidden comment: *)
Capacitor, Ceramic (MLCC), 0.5pF, ±0.25pF, 50V, NP0, ±0.25pF, SMD 0402; Manufacturer: Darfon Elec; Manufacturer Part Number: C1005NP0508CGT
footprint CAP-0402 (0402 (1005M) Capacitor)
pins: 1, 2

## C1005NP0508CGTS
designator C?  Capacitance: 0.5pF  (hidden comment: *)
Capacitor, Ceramic (MLCC), 0.5pF, ±0.25pF, 50V, NP0, ±0.25pF, SMD 0402; Manufacturer: Darfon Elec; Manufacturer Part Number: C1005NP0508CGTS
footprint CAP-0402 (0402 (1005M) Capacitor)
pins: 1, 2

## C1005NP0509CGTS
designator C?  Capacitance: 5pF  (hidden comment: *)
Capacitor, Ceramic (MLCC), 5pF, ±0.25pF, 50V, NP0, ±0.25pF, SMD 0402; Manufacturer: Darfon Elec; Manufacturer Part Number: C1005NP0509CGTS
footprint CAP-0402 (0402 (1005M) Capacitor)
pins: 1, 2

## C1005NP0509DGTS
designator C?  Capacitance: 5pF  (hidden comment: *)
Capacitor, Ceramic (MLCC), 5pF, ±0.5pF, 50V, NP0, ±0.5pF, SMD 0402; Manufacturer: Darfon Elec; Manufacturer Part Number: C1005NP0509DGTS
footprint CAP-0402 (0402 (1005M) Capacitor)
pins: 1, 2

## C1005NP0560JGT
designator C?  Capacitance: 56pF  (hidden comment: *)
Capacitor, Ceramic (MLCC), 56pF, ±5%, 50V, NP0, ±5%, SMD 0402; Manufacturer: Darfon Elec; Manufacturer Part Number: C1005NP0560JGT
footprint CAP-0402 (0402 (1005M) Capacitor)
pins: 1, 2

## C1005NP0560JGTS
designator C?  Capacitance: 56pF  (hidden comment: *)
Capacitor, Ceramic (MLCC), 56pF, ±5%, 50V, NP0, ±5%, SMD 0402; Manufacturer: Darfon Elec; Manufacturer Part Number: C1005NP0560JGTS
footprint CAP-0402 (0402 (1005M) Capacitor)
pins: 1, 2

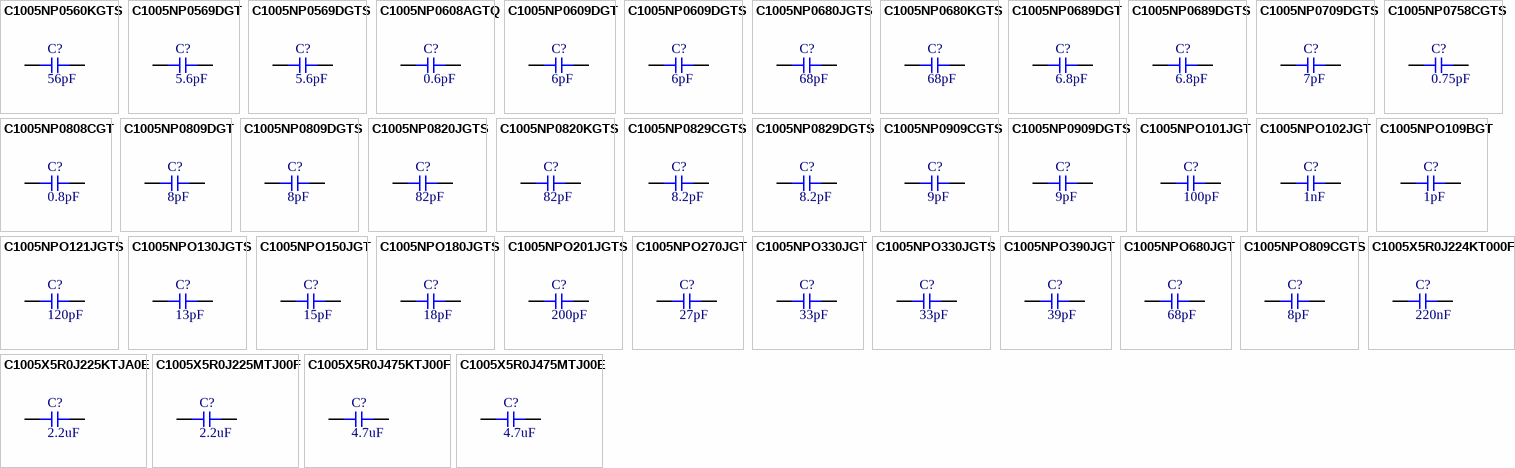
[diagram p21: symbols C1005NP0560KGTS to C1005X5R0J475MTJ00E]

## C1005NP0560KGTS
designator C?  Capacitance: 56pF  (hidden comment: *)
Capacitor, Ceramic (MLCC), 56pF, ±10%, 50V, NP0, ±10%, SMD 0402; Manufacturer: Darfon Elec; Manufacturer Part Number: C1005NP0560KGTS
footprint CAP-0402 (0402 (1005M) Capacitor)
pins: 1, 2

## C1005NP0569DGT
designator C?  Capacitance: 5.6pF  (hidden comment: *)
Capacitor, Ceramic (MLCC), 5.6pF, ±0.5pF, 50V, NP0, ±0.5pF, SMD 0402; Manufacturer: Darfon Elec; Manufacturer Part Number: C1005NP0569DGT
footprint CAP-0402 (0402 (1005M) Capacitor)
pins: 1, 2

## C1005NP0569DGTS
designator C?  Capacitance: 5.6pF  (hidden comment: *)
Capacitor, Ceramic (MLCC), 5.6pF, ±0.5pF, 50V, NP0, ±0.5pF, SMD 0402; Manufacturer: Darfon Elec; Manufacturer Part Number: C1005NP0569DGTS
footprint CAP-0402 (0402 (1005M) Capacitor)
pins: 1, 2

## C1005NP0608AGTQ
designator C?  Capacitance: 0.6pF  (hidden comment: *)
Capacitor, Ceramic (MLCC), 0.6pF, ±0.05pF, 50V, NP0, ±0.05pF, SMD 0402; Manufacturer: Darfon Elec; Manufacturer Part Number: C1005NP0608AGTQ
footprint CAP-0402 (0402 (1005M) Capacitor)
pins: 1, 2

## C1005NP0609DGT
designator C?  Capacitance: 6pF  (hidden comment: *)
Capacitor, Ceramic (MLCC), 6pF, ±0.5pF, 50V, NP0, ±0.5pF, SMD 0402; Manufacturer: Darfon Elec; Manufacturer Part Number: C1005NP0609DGT
footprint CAP-0402 (0402 (1005M) Capacitor)
pins: 1, 2

## C1005NP0609DGTS
designator C?  Capacitance: 6pF  (hidden comment: *)
Capacitor, Ceramic (MLCC), 6pF, ±0.5pF, 50V, NP0, ±0.5pF, SMD 0402; Manufacturer: Darfon Elec; Manufacturer Part Number: C1005NP0609DGTS
footprint CAP-0402 (0402 (1005M) Capacitor)
pins: 1, 2

## C1005NP0680JGTS
designator C?  Capacitance: 68pF  (hidden comment: *)
Capacitor, Ceramic (MLCC), 68pF, ±5%, 50V, NP0, ±5%, SMD 0402; Manufacturer: Darfon Elec; Manufacturer Part Number: C1005NP0680JGTS
footprint CAP-0402 (0402 (1005M) Capacitor)
pins: 1, 2

## C1005NP0680KGTS
designator C?  Capacitance: 68pF  (hidden comment: *)
Capacitor, Ceramic (MLCC), 68pF, ±10%, 50V, NP0, ±10%, SMD 0402; Manufacturer: Darfon Elec; Manufacturer Part Number: C1005NP0680KGTS
footprint CAP-0402 (0402 (1005M) Capacitor)
pins: 1, 2

## C1005NP0689DGT
designator C?  Capacitance: 6.8pF  (hidden comment: *)
Capacitor, Ceramic (MLCC), 6.8pF, ±0.5pF, 50V, NP0, ±0.5pF, SMD 0402; Manufacturer: Darfon Elec; Manufacturer Part Number: C1005NP0689DGT
footprint CAP-0402 (0402 (1005M) Capacitor)
pins: 1, 2

## C1005NP0689DGTS
designator C?  Capacitance: 6.8pF  (hidden comment: *)
Capacitor, Ceramic (MLCC), 6.8pF, ±0.5pF, 50V, NP0, ±0.5pF, SMD 0402; Manufacturer: Darfon Elec; Manufacturer Part Number: C1005NP0689DGTS
footprint CAP-0402 (0402 (1005M) Capacitor)
pins: 1, 2

## C1005NP0709DGTS
designator C?  Capacitance: 7pF  (hidden comment: *)
Capacitor, Ceramic (MLCC), 7pF, ±0.5pF, 50V, NP0, ±0.5pF, SMD 0402; Manufacturer: Darfon Elec; Manufacturer Part Number: C1005NP0709DGTS
footprint CAP-0402 (0402 (1005M) Capacitor)
pins: 1, 2

## C1005NP0758CGTS
designator C?  Capacitance: 0.75pF  (hidden comment: *)
Capacitor, Ceramic (MLCC), 0.75pF, ±0.25pF, 50V, NP0, ±0.25pF, SMD 0402; Manufacturer: Darfon Elec; Manufacturer Part Number: C1005NP0758CGTS
footprint CAP-0402 (0402 (1005M) Capacitor)
pins: 1, 2

## C1005NP0808CGT
designator C?  Capacitance: 0.8pF  (hidden comment: *)
Capacitor, Ceramic (MLCC), 0.8pF, ±0.25pF, 50V, NP0, ±0.25pF, SMD 0402; Manufacturer: Darfon Elec; Manufacturer Part Number: C1005NP0808CGT
footprint CAP-0402 (0402 (1005M) Capacitor)
pins: 1, 2

## C1005NP0809DGT
designator C?  Capacitance: 8pF  (hidden comment: *)
Capacitor, Ceramic (MLCC), 8pF, ±0.5pF, 50V, NP0, ±0.5pF, SMD 0402; Manufacturer: Darfon Elec; Manufacturer Part Number: C1005NP0809DGT
footprint CAP-0402 (0402 (1005M) Capacitor)
pins: 1, 2

## C1005NP0809DGTS
designator C?  Capacitance: 8pF  (hidden comment: *)
Capacitor, Ceramic (MLCC), 8pF, ±0.5pF, 50V, NP0, ±0.5pF, SMD 0402; Manufacturer: Darfon Elec; Manufacturer Part Number: C1005NP0809DGTS
footprint CAP-0402 (0402 (1005M) Capacitor)
pins: 1, 2

## C1005NP0820JGTS
designator C?  Capacitance: 82pF  (hidden comment: *)
Capacitor, Ceramic (MLCC), 82pF, ±5%, 50V, NP0, ±5%, SMD 0402; Manufacturer: Darfon Elec; Manufacturer Part Number: C1005NP0820JGTS
footprint CAP-0402 (0402 (1005M) Capacitor)
pins: 1, 2

## C1005NP0820KGTS
designator C?  Capacitance: 82pF  (hidden comment: *)
Capacitor, Ceramic (MLCC), 82pF, ±10%, 50V, NP0, ±10%, SMD 0402; Manufacturer: Darfon Elec; Manufacturer Part Number: C1005NP0820KGTS
footprint CAP-0402 (0402 (1005M) Capacitor)
pins: 1, 2

## C1005NP0829CGTS
designator C?  Capacitance: 8.2pF  (hidden comment: *)
Capacitor, Ceramic (MLCC), 8.2pF, ±0.25pF, 50V, NP0, ±0.25pF, SMD 0402; Manufacturer: Darfon Elec; Manufacturer Part Number: C1005NP0829CGTS
footprint CAP-0402 (0402 (1005M) Capacitor)
pins: 1, 2

## C1005NP0829DGTS
designator C?  Capacitance: 8.2pF  (hidden comment: *)
Capacitor, Ceramic (MLCC), 8.2pF, ±0.5pF, 50V, NP0, ±0.5pF, SMD 0402; Manufacturer: Darfon Elec; Manufacturer Part Number: C1005NP0829DGTS
footprint CAP-0402 (0402 (1005M) Capacitor)
pins: 1, 2

## C1005NP0909CGTS
designator C?  Capacitance: 9pF  (hidden comment: *)
Capacitor, Ceramic (MLCC), 9pF, ±0.25pF, 50V, NP0, ±0.25pF, SMD 0402; Manufacturer: Darfon Elec; Manufacturer Part Number: C1005NP0909CGTS
footprint CAP-0402 (0402 (1005M) Capacitor)
pins: 1, 2

## C1005NP0909DGTS
designator C?  Capacitance: 9pF  (hidden comment: *)
Capacitor, Ceramic (MLCC), 9pF, ±0.5pF, 50V, NP0, ±0.5pF, SMD 0402; Manufacturer: Darfon Elec; Manufacturer Part Number: C1005NP0909DGTS
footprint CAP-0402 (0402 (1005M) Capacitor)
pins: 1, 2

## C1005NPO101JGT
designator C?  Capacitance: 100pF  (hidden comment: *)
Capacitor, Ceramic (MLCC), 100pF, ±5%, 50V, NP0, ±5%, SMD 0402; Manufacturer: Darfon Elec; Manufacturer Part Number: C1005NPO101JGT
footprint CAP-0402 (0402 (1005M) Capacitor)
pins: 1, 2

## C1005NPO102JGT
designator C?  Capacitance: 1nF  (hidden comment: *)
Capacitor, Ceramic (MLCC), 1nF, ±5%, 50V, NP0, ±5%, SMD 0402; Manufacturer: Darfon Elec; Manufacturer Part Number: C1005NPO102JGT
footprint CAP-0402 (0402 (1005M) Capacitor)
pins: 1, 2

## C1005NPO109BGT
designator C?  Capacitance: 1pF  (hidden comment: *)
Capacitor, Ceramic (MLCC), 1pF, ±0.1pF, 50V, NP0, ±0.1pF, SMD 0402; Manufacturer: Darfon Elec; Manufacturer Part Number: C1005NPO109BGT
footprint CAP-0402 (0402 (1005M) Capacitor)
pins: 1, 2

## C1005NPO121JGTS
designator C?  Capacitance: 120pF  (hidden comment: *)
Capacitor, Ceramic (MLCC), 120pF, ±5%, 50V, NP0, ±5%, SMD 0402; Manufacturer: Darfon Elec; Manufacturer Part Number: C1005NPO121JGTS
footprint CAP-0402 (0402 (1005M) Capacitor)
pins: 1, 2

## C1005NPO130JGTS
designator C?  Capacitance: 13pF  (hidden comment: *)
Capacitor, Ceramic (MLCC), 13pF, ±5%, 50V, NP0, ±5%, SMD 0402; Manufacturer: Darfon Elec; Manufacturer Part Number: C1005NPO130JGTS
footprint CAP-0402 (0402 (1005M) Capacitor)
pins: 1, 2

## C1005NPO150JGT
designator C?  Capacitance: 15pF  (hidden comment: *)
Capacitor, Ceramic (MLCC), 15pF, ±5%, 50V, NP0, ±5%, SMD 0402; Manufacturer: Darfon Elec; Manufacturer Part Number: C1005NPO150JGT
footprint CAP-0402 (0402 (1005M) Capacitor)
pins: 1, 2

## C1005NPO180JGTS
designator C?  Capacitance: 18pF  (hidden comment: *)
Capacitor, Ceramic (MLCC), 18pF, ±5%, 50V, NP0, ±5%, SMD 0402; Manufacturer: Darfon Elec; Manufacturer Part Number: C1005NPO180JGTS
footprint CAP-0402 (0402 (1005M) Capacitor)
pins: 1, 2

## C1005NPO201JGTS
designator C?  Capacitance: 200pF  (hidden comment: *)
Capacitor, Ceramic (MLCC), 200pF, ±5%, 50V, NP0, ±5%, SMD 0402; Manufacturer: Darfon Elec; Manufacturer Part Number: C1005NPO201JGTS
footprint CAP-0402 (0402 (1005M) Capacitor)
pins: 1, 2

## C1005NPO270JGT
designator C?  Capacitance: 27pF  (hidden comment: *)
Capacitor, Ceramic (MLCC), 27pF, ±5%, 50V, NP0, ±5%, SMD 0402; Manufacturer: Darfon Elec; Manufacturer Part Number: C1005NPO270JGT
footprint CAP-0402 (0402 (1005M) Capacitor)
pins: 1, 2

## C1005NPO330JGT
designator C?  Capacitance: 33pF  (hidden comment: *)
Capacitor, Ceramic (MLCC), 33pF, ±5%, 50V, NP0, ±5%, SMD 0402; Manufacturer: Darfon Elec; Manufacturer Part Number: C1005NPO330JGT
footprint CAP-0402 (0402 (1005M) Capacitor)
pins: 1, 2

## C1005NPO330JGTS
designator C?  Capacitance: 33pF  (hidden comment: *)
Capacitor, Ceramic (MLCC), 33pF, ±5%, 50V, NP0, ±5%, SMD 0402; Manufacturer: Darfon Elec; Manufacturer Part Number: C1005NPO330JGTS
footprint CAP-0402 (0402 (1005M) Capacitor)
pins: 1, 2

## C1005NPO390JGT
designator C?  Capacitance: 39pF  (hidden comment: *)
Capacitor, Ceramic (MLCC), 39pF, ±5%, 50V, NP0, ±5%, SMD 0402; Manufacturer: Darfon Elec; Manufacturer Part Number: C1005NPO390JGT
footprint CAP-0402 (0402 (1005M) Capacitor)
pins: 1, 2

## C1005NPO680JGT
designator C?  Capacitance: 68pF  (hidden comment: *)
Capacitor, Ceramic (MLCC), 68pF, ±5%, 50V, NP0, ±5%, SMD 0402; Manufacturer: Darfon Elec; Manufacturer Part Number: C1005NPO680JGT
footprint CAP-0402 (0402 (1005M) Capacitor)
pins: 1, 2

## C1005NPO809CGTS
designator C?  Capacitance: 8pF  (hidden comment: *)
Capacitor, Ceramic (MLCC), 8pF, ±0.25pF, 50V, NP0, ±0.25pF, SMD 0402; Manufacturer: Darfon Elec; Manufacturer Part Number: C1005NPO809CGTS
footprint CAP-0402 (0402 (1005M) Capacitor)
pins: 1, 2

## C1005X5R0J224KT000F
designator C?  Capacitance: 220nF  (hidden comment: *)
Capacitor, Ceramic (MLCC), 220nF, ±10%, 6.3V, X5R, ±10%, SMD 0402; Manufacturer: TDK; Manufacturer Part Number: C1005X5R0J224KT000F
footprint CAP-0402 (0402 (1005M) Capacitor)
pins: 1, 2

## C1005X5R0J225KTJA0E
designator C?  Capacitance: 2.2uF  (hidden comment: *)
Capacitor, Ceramic (MLCC), 2.2uF, ±10%, 6.3V, X5R, ±10%, SMD 0402; Manufacturer: TDK; Manufacturer Part Number: C1005X5R0J225KTJA0E
footprint CAP-0402 (0402 (1005M) Capacitor)
pins: 1, 2

## C1005X5R0J225MTJ00F
designator C?  Capacitance: 2.2uF  (hidden comment: *)
Capacitor, Ceramic (MLCC), 2.2uF, ±20%, 6.3V, X5R, ±20%, SMD 0402; Manufacturer: TDK; Manufacturer Part Number: C1005X5R0J225MTJ00F
footprint CAP-0402 (0402 (1005M) Capacitor)
pins: 1, 2

## C1005X5R0J475KTJ00F
designator C?  Capacitance: 4.7uF  (hidden comment: *)
Capacitor, Ceramic (MLCC), 4.7uF, ±10%, 6.3V, X5R, ±10%, SMD 0402; Manufacturer: TDK; Manufacturer Part Number: C1005X5R0J475KTJ00F
footprint CAP-0402 (0402 (1005M) Capacitor)
pins: 1, 2

## C1005X5R0J475MTJ00E
designator C?  Capacitance: 4.7uF  (hidden comment: *)
Capacitor, Ceramic (MLCC), 4.7uF, ±20%, 6.3V, X5R, ±20%, SMD 0402; Manufacturer: TDK; Manufacturer Part Number: C1005X5R0J475MTJ00E
footprint CAP-0402 (0402 (1005M) Capacitor)
pins: 1, 2

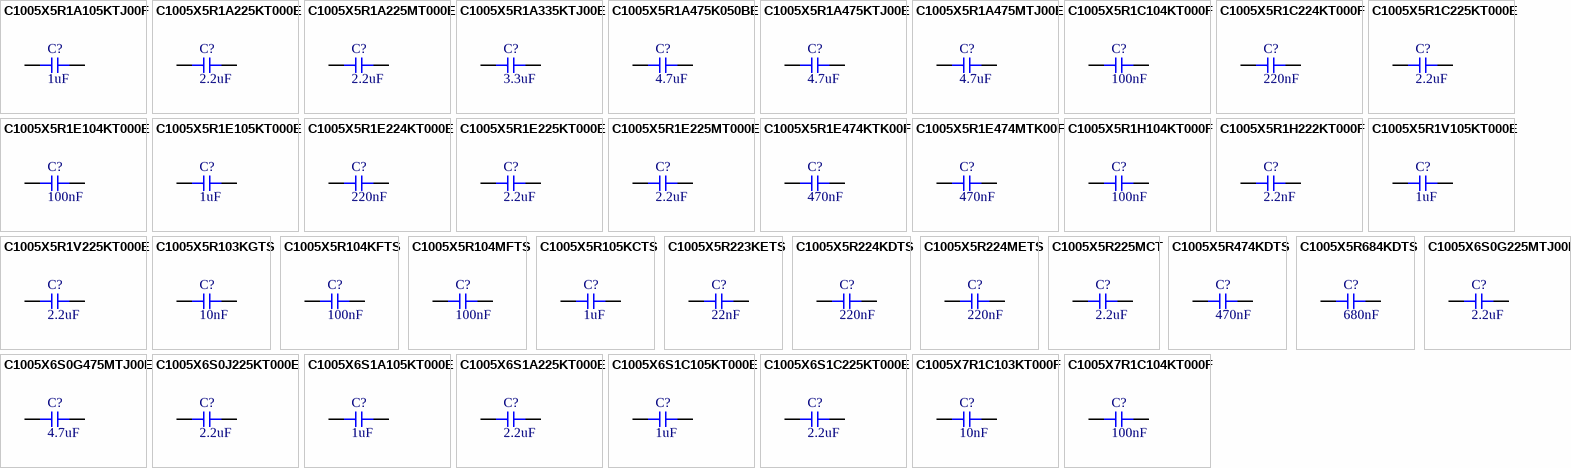
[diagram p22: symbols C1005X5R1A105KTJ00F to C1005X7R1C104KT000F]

## C1005X5R1A105KTJ00F
designator C?  Capacitance: 1uF  (hidden comment: *)
Capacitor, Ceramic (MLCC), 1uF, ±10%, 10V, X5R, ±10%, SMD 0402; Manufacturer: TDK; Manufacturer Part Number: C1005X5R1A105KTJ00F
footprint CAP-0402 (0402 (1005M) Capacitor)
pins: 1, 2

## C1005X5R1A225KT000E
designator C?  Capacitance: 2.2uF  (hidden comment: *)
Capacitor, Ceramic (MLCC), 2.2uF, ±10%, 10V, X5R, ±10%, SMD 0402; Manufacturer: TDK; Manufacturer Part Number: C1005X5R1A225KT000E
footprint CAP-0402 (0402 (1005M) Capacitor)
pins: 1, 2

## C1005X5R1A225MT000E
designator C?  Capacitance: 2.2uF  (hidden comment: *)
Capacitor, Ceramic (MLCC), 2.2uF, ±20%, 10V, X5R, ±20%, SMD 0402; Manufacturer: TDK; Manufacturer Part Number: C1005X5R1A225MT000E
footprint CAP-0402 (0402 (1005M) Capacitor)
pins: 1, 2

## C1005X5R1A335KTJ00E
designator C?  Capacitance: 3.3uF  (hidden comment: *)
Capacitor, Ceramic (MLCC), 3.3uF, ±10%, 10V, X5R, ±10%, SMD 0402; Manufacturer: TDK; Manufacturer Part Number: C1005X5R1A335KTJ00E
footprint CAP-0402 (0402 (1005M) Capacitor)
pins: 1, 2

## C1005X5R1A475K050BE
designator C?  Capacitance: 4.7uF  (hidden comment: *)
Capacitor, Ceramic (MLCC), 4.7uF, ±10%, 10V, ±10%, SMD 0402; Manufacturer: TDK; Manufacturer Part Number: C1005X5R1A475K050BE
footprint CAP-0402 (0402 (1005M) Capacitor)
pins: 1, 2

## C1005X5R1A475KTJ00E
designator C?  Capacitance: 4.7uF  (hidden comment: *)
Capacitor, Ceramic (MLCC), 4.7uF, ±10%, 10V, X5R, ±10%, SMD 0402; Manufacturer: TDK; Manufacturer Part Number: C1005X5R1A475KTJ00E
footprint CAP-0402 (0402 (1005M) Capacitor)
pins: 1, 2

## C1005X5R1A475MTJ00E
designator C?  Capacitance: 4.7uF  (hidden comment: *)
Capacitor, Ceramic (MLCC), 4.7uF, ±20%, 10V, X5R, ±20%, SMD 0402; Manufacturer: TDK; Manufacturer Part Number: C1005X5R1A475MTJ00E
footprint CAP-0402 (0402 (1005M) Capacitor)
pins: 1, 2

## C1005X5R1C104KT000F
designator C?  Capacitance: 100nF  (hidden comment: *)
Capacitor, Ceramic (MLCC), 100nF, ±10%, 16V, X5R, ±10%, SMD 0402; Manufacturer: TDK; Manufacturer Part Number: C1005X5R1C104KT000F
footprint CAP-0402 (0402 (1005M) Capacitor)
pins: 1, 2

## C1005X5R1C224KT000F
designator C?  Capacitance: 220nF  (hidden comment: *)
Capacitor, Ceramic (MLCC), 220nF, ±10%, 16V, X5R, ±10%, SMD 0402; Manufacturer: TDK; Manufacturer Part Number: C1005X5R1C224KT000F
footprint CAP-0402 (0402 (1005M) Capacitor)
pins: 1, 2

## C1005X5R1C225KT000E
designator C?  Capacitance: 2.2uF  (hidden comment: *)
Capacitor, Ceramic (MLCC), 2.2uF, ±10%, 16V, X5R, ±10%, SMD 0402; Manufacturer: TDK; Manufacturer Part Number: C1005X5R1C225KT000E
footprint CAP-0402 (0402 (1005M) Capacitor)
pins: 1, 2

## C1005X5R1E104KT000E
designator C?  Capacitance: 100nF  (hidden comment: *)
Capacitor, Ceramic (MLCC), 100nF, ±10%, 25V, X5R, ±10%, SMD 0402; Manufacturer: TDK; Manufacturer Part Number: C1005X5R1E104KT000E
footprint CAP-0402 (0402 (1005M) Capacitor)
pins: 1, 2

## C1005X5R1E105KT000E
designator C?  Capacitance: 1uF  (hidden comment: *)
Capacitor, Ceramic (MLCC), 1uF, ±10%, 25V, X5R, ±10%, SMD 0402; Manufacturer: TDK; Manufacturer Part Number: C1005X5R1E105KT000E
footprint CAP-0402 (0402 (1005M) Capacitor)
pins: 1, 2

## C1005X5R1E224KT000E
designator C?  Capacitance: 220nF  (hidden comment: *)
Capacitor, Ceramic (MLCC), 220nF, ±10%, 25V, X5R, ±10%, SMD 0402; Manufacturer: TDK; Manufacturer Part Number: C1005X5R1E224KT000E
footprint CAP-0402 (0402 (1005M) Capacitor)
pins: 1, 2

## C1005X5R1E225KT000E
designator C?  Capacitance: 2.2uF  (hidden comment: *)
Capacitor, Ceramic (MLCC), 2.2uF, ±10%, 25V, X5R, ±10%, SMD 0402; Manufacturer: TDK; Manufacturer Part Number: C1005X5R1E225KT000E
footprint CAP-0402 (0402 (1005M) Capacitor)
pins: 1, 2

## C1005X5R1E225MT000E
designator C?  Capacitance: 2.2uF  (hidden comment: *)
Capacitor, Ceramic (MLCC), 2.2uF, ±20%, 25V, X5R, ±20%, SMD 0402; Manufacturer: TDK; Manufacturer Part Number: C1005X5R1E225MT000E
footprint CAP-0402 (0402 (1005M) Capacitor)
pins: 1, 2

## C1005X5R1E474KTK00F
designator C?  Capacitance: 470nF  (hidden comment: *)
Capacitor, Ceramic (MLCC), 470nF, ±10%, 25V, X5R, ±10%, SMD 0402; Manufacturer: TDK; Manufacturer Part Number: C1005X5R1E474KTK00F
footprint CAP-0402 (0402 (1005M) Capacitor)
pins: 1, 2

## C1005X5R1E474MTK00F
designator C?  Capacitance: 470nF  (hidden comment: *)
Capacitor, Ceramic (MLCC), 470nF, ±20%, 25V, X5R, ±20%, SMD 0402; Manufacturer: TDK; Manufacturer Part Number: C1005X5R1E474MTK00F
footprint CAP-0402 (0402 (1005M) Capacitor)
pins: 1, 2

## C1005X5R1H104KT000F
designator C?  Capacitance: 100nF  (hidden comment: *)
Capacitor, Ceramic (MLCC), 100nF, ±10%, 50V, X5R, ±10%, SMD 0402; Manufacturer: TDK; Manufacturer Part Number: C1005X5R1H104KT000F
footprint CAP-0402 (0402 (1005M) Capacitor)
pins: 1, 2

## C1005X5R1H222KT000F
designator C?  Capacitance: 2.2nF  (hidden comment: *)
Capacitor, Ceramic (MLCC), 2.2nF, ±10%, 50V, X5R, ±10%, SMD 0402; Manufacturer: TDK; Manufacturer Part Number: C1005X5R1H222KT000F
footprint CAP-0402 (0402 (1005M) Capacitor)
pins: 1, 2

## C1005X5R1V105KT000E
designator C?  Capacitance: 1uF  (hidden comment: *)
Capacitor, Ceramic (MLCC), 1uF, ±10%, 35V, X5R, ±10%, SMD 0402; Manufacturer: TDK; Manufacturer Part Number: C1005X5R1V105KT000E
footprint CAP-0402 (0402 (1005M) Capacitor)
pins: 1, 2

## C1005X5R1V225KT000E
designator C?  Capacitance: 2.2uF  (hidden comment: *)
Capacitor, Ceramic (MLCC), 2.2uF, ±10%, 35V, X5R, ±10%, SMD 0402; Manufacturer: TDK; Manufacturer Part Number: C1005X5R1V225KT000E
footprint CAP-0402 (0402 (1005M) Capacitor)
pins: 1, 2

## C1005X5R103KGTS
designator C?  Capacitance: 10nF  (hidden comment: *)
Capacitor, Ceramic (MLCC), 10nF, ±10%, 50V, X5R, ±10%, SMD 0402; Manufacturer: Darfon Elec; Manufacturer Part Number: C1005X5R103KGTS
footprint CAP-0402 (0402 (1005M) Capacitor)
pins: 1, 2

## C1005X5R104KFTS
designator C?  Capacitance: 100nF  (hidden comment: *)
Capacitor, Ceramic (MLCC), 100nF, ±10%, 25V, X5R, ±10%, SMD 0402; Manufacturer: Darfon Elec; Manufacturer Part Number: C1005X5R104KFTS
footprint CAP-0402 (0402 (1005M) Capacitor)
pins: 1, 2

## C1005X5R104MFTS
designator C?  Capacitance: 100nF  (hidden comment: *)
Capacitor, Ceramic (MLCC), 100nF, ±20%, 25V, X5R, ±20%, SMD 0402; Manufacturer: Darfon Elec; Manufacturer Part Number: C1005X5R104MFTS
footprint CAP-0402 (0402 (1005M) Capacitor)
pins: 1, 2

## C1005X5R105KCTS
designator C?  Capacitance: 1uF  (hidden comment: *)
Capacitor, Ceramic (MLCC), 1uF, ±10%, 6.3V, X5R, ±10%, SMD 0402; Manufacturer: Darfon Elec; Manufacturer Part Number: C1005X5R105KCTS
footprint CAP-0402 (0402 (1005M) Capacitor)
pins: 1, 2

## C1005X5R223KETS
designator C?  Capacitance: 22nF  (hidden comment: *)
Capacitor, Ceramic (MLCC), 22nF, ±10%, 16V, X5R, ±10%, SMD 0402; Manufacturer: Darfon Elec; Manufacturer Part Number: C1005X5R223KETS
footprint CAP-0402 (0402 (1005M) Capacitor)
pins: 1, 2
